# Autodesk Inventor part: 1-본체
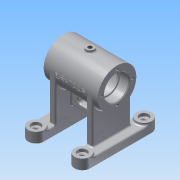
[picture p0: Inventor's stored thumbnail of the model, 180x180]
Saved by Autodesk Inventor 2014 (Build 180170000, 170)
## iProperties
Created: 2015-11
Part Number: 1-본체
Material: 알루미늄 6061
Document SubType Name: Modeling
Designer: 103-15
Density: 2.71 g/cm^3
Appearance: 알루미늄 - 평지
Mass: 357.75 g
Surface Area: 463.164 cm^2
Volume: 132.011 cm^3
Author: 103-15
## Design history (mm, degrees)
sketch "스케치1"
  geometry: L1 (-35, 0)-(35, 0); L2 (-35, 0)-(-35, 25); L3 (-35, 25)-(35, 25); L4 (35, 25)-(35, 0); L5 (-21, 0)-(-21, 21); L6 (-21, 21)-(21, 21); L7 (21, 21)-(21, 0); 3 further points
  constraints: 14 end point, 4 perpendicular, 2 midpoint, 2 parallel, 2 point on line, 1 coincident, 1 horizontal, 1 vertical alignment
  dimensions: "d0" = 70 distance of L1.start L1.end; "d1" = 50 diameter of L3 L1; "d16" = 42 diameter of L6 L1; "d17" = 42 distance between parallel lines of L7 L5
revolve "회전1" sketch "스케치1" stored, may be unused: angle "d2" = 90 deg
node "작업 평면1"
sketch "스케치2"
  geometry: L1 (30, -50)-(-30, -50); L2 (-40, -40)-(-40, 40); L3 (-30, 50)-(30, 50); L4 (40, 40)-(40, -40); L5 (40, -50)-(-40, 50); L6 (-40, -50)-(40, 50); L7 (-20, 40)-(-20, -40); L8 (20, -40)-(20, 40); A1 r 10 centre (-30, 40) between (-40, 40) and (-30, 50); A2 r 10 centre (-30, -40) between (-30, -50) and (-40, -40); A3 r 10 centre (30, -40) between (40, -40) and (30, -50); A4 r 10 centre (30, 40) between (30, 50) and (40, 40); 1 further point
  constraints: 16 end point, 12 point on circle, 11 tangent, 8 point on line, 4 centre point, 3 equal radius, 3 parallel, 2 midpoint, 1 horizontal, 1 perpendicular
  dimensions: "d4" = 100 distance of L6.start L5.end; "d5" = 80 distance of L5.start L6.start; "d6" = 10 radius of A1
extrude "돌출1" join sketch "스케치2" distance "d7" = 10; taper "d8" = 0 deg
extrude "돌출2" join sketch "스케치2" distance "d9" = 13; taper "d10" = 0 deg
node "작업 평면3"
sketch "스케치3"
  geometry: L1 (0, 10)-(80, 10) reference; L2 (15, 68)-(15, 10); L3 (65, 68)-(65, 10); A1 r 25 centre (40, 68) between (15, 68) and (65, 68) reference; 1 further point
  constraints: 4 end point, 2 perpendicular, 2 point on circle, 2 point on line, 2 tangent
extrude "돌출3" join sketch "스케치3" distance "d12" = 8; taper "d13" = 0 deg
node "작업 평면4"
hole "구멍1" diameter "d20" = 28; stored, may be unused: countersink angle "d24" = 90 deg, drill point angle "d26" = 118 deg; dims "d18" = 10, "d19" = 10, "d21" = 6, "d22" = 32, "d23" = 12, "d25" = 8
sketch "스케치4"
  geometry: C1 r 16 at (0, 0) reference; 1 further point
  constraints: 1 horizontal alignment
  dimensions: "d27" = 20 distance of C1.centre point (-20, 0)
hole "구멍2" sketch "스케치4" at (-20, 0) diameter "d28" = 3.242; stored, may be unused: countersink angle "d32" = 90 deg, drill point angle "d34" = 118 deg; dims "d29" = 8, "d30" = 32, "d31" = 12, "d33" = 10
node "작업 평면5"
sketch "스케치5"
  geometry: C1 r 10 at (0, 0) reference; C2 r 10 at (-60, 80) reference; C3 r 10 at (0, 80) reference; C4 r 10 at (-60, 0) reference; 5 further points
  constraints: 4 coincident
hole "구멍3" sketch "스케치5" at (-60, 80), (0, 80), (-60, 0), (0, 0) diameter "d39" = 6; stored, may be unused: countersink angle "d43" = 90 deg, drill point angle "d45" = 118 deg; dims "d40" = 8, "d41" = 12, "d42" = 4, "d44" = 10
node "작업 평면6"
sketch "스케치6"
  geometry: C1 r 5 at (0, 0); 1 further point
  constraints: 1 centre point, 1 coincident
  dimensions: "d47" = 10 diameter of C1
extrude "돌출4" join sketch "스케치6" stored distance "d48" = 8; taper "d49" = 0 deg
hole "구멍4" diameter "d52" = 5.188; stored, may be unused: countersink angle "d56" = 90 deg, drill point angle "d58" = 118 deg; dims "d53" = 8, "d54" = 6, "d55" = 4, "d57" = 10, "d59" = 10, "d60" = 10
node "작업 평면7"
sketch "스케치7"
  geometry: L1 (35, -25)-(-35, -25) reference; L2 (-20, 0)-(-20, -58) reference; L3 (-28, -58)-(-20, -58) reference; L4 (-28, 0)-(-28, -58) reference; L5 (-20, 0)-(-28, 0) reference; L6 (20, 0)-(20, -58) reference; L7 (-20, -45)-(20, -45); L8 (-20, -45)-(-20, -22.036); L9 (-20, -22.036)-(20, -22.036); L10 (20, -45)-(20, -22.036); L11 (-8, -31.5)-(8, -31.5); L12 (8, -38.5)-(-8, -38.5); L13 (33, -68)-(27, -68) reference; A1 r 3.5 centre (-8, -35) between (-8, -31.5) and (-8, -38.5); A2 r 3.5 centre (8, -35) between (8, -38.5) and (8, -31.5); 2 further points
  constraints: 12 end point, 4 point on circle, 4 point on line, 3 perpendicular, 2 centre point, 2 tangent, 1 collinear, 1 equal radius, 1 horizontal alignment, 1 midpoint, 1 parallel, 1 vertical alignment
  dimensions: "d62" = 20 distance between parallel lines of L7 L1; "d63" = 22.96425 distance between parallel lines of L7 L9; "d64" = 3.5 radius of A1; "d65" = 23 dimension on A2 A1; "d66" = 33 distance from line of L13 A2.centre
extrude "돌출5" join sketch "스케치7" stored distance "d67" = 8; taper "d68" = 0 deg
node "작업 평면8"
sketch "스케치8"
  geometry: L1 (0, 0)-(0, -25); L2 (0, 0)-(14, -24.249); 1 further point
  constraints: 4 end point, 1 vertical, 1 vertical alignment, 1 other
  dimensions: "d70" = 28 distance of L1.start L2.end; "d71" = 30 deg angle of L2 L1
node "작업 평면9"
sketch "스케치9"
  geometry: C1 r 6 at (0, 0); 1 further point
  constraints: 1 centre point, 1 coincident
  dimensions: "d72" = 12 diameter of C1
extrude "돌출6" join sketch "스케치9" stored distance "d73" = 8; taper "d74" = 0 deg
hole "구멍5" diameter "d77" = 5.188; stored, may be unused: countersink angle "d81" = 90 deg, drill point angle "d83" = 118 deg; dims "d75" = 10, "d76" = 10, "d78" = 8, "d79" = 6, "d80" = 4, "d82" = 10
node "작업 평면10"
sketch "스케치10"
  geometry: 2 further points
  constraints: 1 coincident, 1 other
feature "엠보싱1" sketch "스케치10" dims "d0" = 70, "d84" = 0.5, "d85" = 0
chamfer "모따기1" distance "d86" = 1; stored, may be unused: second distance "d87" = 2, angle "d88" = 45 deg
fillet "모깎기1" dims "d89" = 0.3, "d90" = 2, "d94" = 3
fillet "모깎기3" dims "d92" = 2
fillet "모깎기4" dims "d93" = 2
node "솔리드1"
mirror "대칭1"
pattern_circular "원형 패턴1" dims angle "d36" = 360 deg
mirror "대칭2"
node "투영된 루프1"
node "투영된 루프2"
node "투영된 루프3"
other parameters: "d3" = -68, "d11" = 0, "d14" = 0, "d38" = 0, "d46" = -96, "d61" = 0, "d69" = 0
